Omron CX-Programmer project NewProject (CX-Programmer 9.11)

# PLC NewPLC1: CP1L M

## Global symbols (name address type ; comment)
AbsoluteActualPosition D0 DINT  ; Absolute Actual Position
ActualVelocity D2 DINT  ; Actual Velocity
A641.00 BOOL  ; $?St$Bk?_#[4] / Modbus-RTU Master Execution Bit / Turned ON: Execution Started / ON: Execution In Progress / OFF: Not Executed Or Execution completed.$?St$Bk?_#[4]
A641.01 BOOL  ; $?St$Bk?_#[5] / Modbus-RTU Master Execution Normal Flag / ON: Execution Normal / OFF: Execution Error Or Still In Progress$?St$Bk?_#[5]
A641.02 BOOL  ; $?St$Bk?_#[6] / Modbus-RTU Master Execution Error Flag / ON: Execution Error / OFF: Execution Normal Or Still In Progress$?St$Bk?_#[6]
D100 CHANNEL  ; Number Of Modbus Data Bytes
H0 CHANNEL  ; Input Status
H0.00 BOOL  ; Input 1
H0.01 BOOL  ; Input 2
H0.02 BOOL  ; Input 3
H0.03 BOOL  ; Input 4
H0.04 BOOL  ; Input 5
H0.05 BOOL  ; Input 6
H0.06 BOOL  ; Input 7
H0.07 BOOL  ; Input 8
H1 CHANNEL  ; Input Status
H10 CHANNEL  ; Output Status
H10.00 BOOL  ; Output 1
H10.01 BOOL  ; Output 2
H10.02 BOOL  ; Output 3
H10.03 BOOL  ; Output 4
H10.04 BOOL  ; Output 5
H10.05 BOOL  ; Output 6
H10.06 BOOL  ; Output 7
H10.07 BOOL  ; Output 8
H1.08 BOOL  ; Input 9
H1.09 BOOL  ; Input 10
H1.10 BOOL  ; Input 11
H1.11 BOOL  ; Input 12
H1.12 BOOL  ; Input 13
H1.13 BOOL  ; Input 14
H1.14 BOOL  ; Input 15
H1.15 BOOL  ; Input 16
H20 CHANNEL  ; Fault / Status Flags
H20.00 BOOL  ; $?St$Bk?_#[7] / Counter-Clockwise Limit Active (No Fault) "L02"$?St$Bk?_#[7]
H20.01 BOOL  ; $?St$Bk?_#[8] / Drive Enabled Condition "E"$?St$Bk?_#[8]
H21 CHANNEL  ; Fault / Status Flags
H21.00 BOOL  ; $?St$Bk?_#[9] / Encoder Feedback / Commutation Fault "F07"$?St$Bk?_#[9]
H21.01 BOOL  ; $?St$Bk?_#[10] / Fatal PLC Fault "F98"$?St$Bk?_#[10]
H21.02 BOOL  ; $?St$Bk?_#[11] / Fatal Sequence Program Fault "F97"$?St$Bk?_#[11]
H21.03 BOOL  ; $?St$Bk?_#[12] / Phasing Fault (Non-Fatal) "F51"$?St$Bk?_#[12]
H21.04 BOOL  ; $?St$Bk?_#[13] / Drive Over-Current Fault (Non-Fatal) "F52"$?St$Bk?_#[13]
H21.05 BOOL  ; $?St$Bk?_#[14] / Motor Over-Current Fault (Non-Fatal) "F53"$?St$Bk?_#[14]
H21.06 BOOL  ; $?St$Bk?_#[15] / Bus Under-Voltage Fault (Non-Fatal) "F54"$?St$Bk?_#[15]
H21.07 BOOL  ; $?St$Bk?_#[16] / Maximum Following-Error Fault (Non-Fatal) "F55"$?St$Bk?_#[16]
H21.08 BOOL  ; $?St$Bk?_#[17] / Velocity Regulation Fault (Non-Fatal) "F56"$?St$Bk?_#[17]
H21.09 BOOL  ; $?St$Bk?_#[18] / Serial Communications Fault (Non-Fatal) "F57"$?St$Bk?_#[18]
H21.10 BOOL  ; $?St$Bk?_#[19] / Positive Travel Limit Fault (Non-Fatal) "FL1"$?St$Bk?_#[19]
H21.11 BOOL  ; $?St$Bk?_#[20] / Negative Travel Limit Fault (Non-Fatal) "FL2"$?St$Bk?_#[20]
H21.12 BOOL  ; $?St$Bk?_#[21] / Sequential Program Execution Fault (Non-Fatal) "F58"$?St$Bk?_#[21]
H21.13 BOOL  ; $?St$Bk?_#[22] / Drive Disabled Condition "d"$?St$Bk?_#[22]
H21.14 BOOL  ; $?St$Bk?_#[23] / Phasing In Progress "P"$?St$Bk?_#[23]
H21.15 BOOL  ; $?St$Bk?_#[24] / Clockwise Travel Limit Active (No Fault) "L01"$?St$Bk?_#[24]
H22 CHANNEL  ; Fault / Status Flags
H22.00 BOOL  ; $?St$Bk?_#[25] / Processor Fault "F00"$?St$Bk?_#[25]
H22.01 BOOL  ; $?St$Bk?_#[26] / Drive Not Configured "F99"$?St$Bk?_#[26]
H22.03 BOOL  ; $?St$Bk?_#[28] / Bridge Hardware Fault "F02"$?St$Bk?_#[28]
H22.04 BOOL  ; $?St$Bk?_#[29] / Current Feedback Fault "F03"$?St$Bk?_#[29]
H22.05 BOOL  ; $?St$Bk?_#[30] / Current Regulation Fault "F04"$?St$Bk?_#[30]
H22.06 BOOL  ; $?St$Bk?_#[31] / Drive Over-Temperature Fault "F05"$?St$Bk?_#[31]
H22.07 BOOL  ; $?St$Bk?_#[32] / Motor Over-Temperature Fault "F06"$?St$Bk?_#[32]
W0.00 BOOL  ; Run Program 1
W0.01 BOOL  ; Run Program 2
W10.00 BOOL  ; Input 1
W10.01 BOOL  ; Input 2
W10.02 BOOL  ; Input 3
W10.03 BOOL  ; Input 4
W10.04 BOOL  ; Input 5
W10.05 BOOL  ; Input 6
W10.06 BOOL  ; Input 7
W10.07 BOOL  ; Input 8
W10.08 BOOL  ; Input 9
W10.09 BOOL  ; Input 10
W10.10 BOOL  ; Input 11
W10.11 BOOL  ; Input 12
W10.12 BOOL  ; Input 13
W10.13 BOOL  ; Input 14
W10.14 BOOL  ; Input 15
W10.15 BOOL  ; Input 16
W1.00 BOOL  ; Read Inputs
W1.01 BOOL  ; Read Outputs
W20.00 BOOL  ; Output 1
W20.01 BOOL  ; Output 2
W20.02 BOOL  ; Output 3
W20.03 BOOL  ; Output 4
W20.04 BOOL  ; Output 5
W20.05 BOOL  ; Output 6
W20.06 BOOL  ; Output 7
W20.07 BOOL  ; Output 8
W21.00 BOOL  ; $?St$Bk?_#[33] / Encoder Feedback / Commutation Fault "F07"$?St$Bk?_#[33]
W21.01 BOOL  ; $?St$Bk?_#[34] / Fatal PLC Fault "F98"$?St$Bk?_#[34]
W21.02 BOOL  ; $?St$Bk?_#[35] / Fatal Sequence Program Fault "F97"$?St$Bk?_#[35]
W21.03 BOOL  ; $?St$Bk?_#[36] / Phasing Fault (Non-Fatal) "F51"$?St$Bk?_#[36]
W21.04 BOOL  ; $?St$Bk?_#[37] / Drive Over-Current Fault (Non-Fatal) "F52"$?St$Bk?_#[37]
W21.05 BOOL  ; $?St$Bk?_#[38] / Motor Over-Current Fault (Non-Fatal) "F53"$?St$Bk?_#[38]
W21.06 BOOL  ; $?St$Bk?_#[39] / Bus Under-Voltage Fault (Non-Fatal) "F54"$?St$Bk?_#[39]
W21.07 BOOL  ; $?St$Bk?_#[40] / Maximum Following-Error Fault (Non-Fatal) "F55"$?St$Bk?_#[40]
W21.08 BOOL  ; $?St$Bk?_#[41] / Velocity Regulation Fault (Non-Fatal) "F56"$?St$Bk?_#[41]
W21.09 BOOL  ; $?St$Bk?_#[42] / Serial Communications Fault (Non-Fatal) "F57"$?St$Bk?_#[42]
W21.10 BOOL  ; $?St$Bk?_#[43] / Positive Travel Limit Fault (Non-Fatal) "FL1"$?St$Bk?_#[43]
W21.11 BOOL  ; $?St$Bk?_#[44] / Negative Travel Limit Fault (Non-Fatal) "FL2"$?St$Bk?_#[44]
W21.12 BOOL  ; $?St$Bk?_#[45] / Sequential Program Execution Fault (Non-Fatal) "F58"$?St$Bk?_#[45]
W21.13 BOOL  ; $?St$Bk?_#[46] / Drive Disabled Condition "d"$?St$Bk?_#[46]
W21.14 BOOL  ; $?St$Bk?_#[47] / Phasing In Progress "P"$?St$Bk?_#[47]
W21.15 BOOL  ; $?St$Bk?_#[48] / Clockwise Travel Limit Active (No Fault) "L01"$?St$Bk?_#[48]
W22.00 BOOL  ; $?St$Bk?_#[49] / Processor Fault "F00"$?St$Bk?_#[49]
W22.01 BOOL  ; $?St$Bk?_#[50] / Drive Not Configured "F99"$?St$Bk?_#[50]
W22.03 BOOL  ; $?St$Bk?_#[52] / Bridge Hardware Fault "F02"$?St$Bk?_#[52]
W22.04 BOOL  ; $?St$Bk?_#[53] / Current Feedback Fault "F03"$?St$Bk?_#[53]
W22.05 BOOL  ; $?St$Bk?_#[54] / Current Regulation Fault "F04"$?St$Bk?_#[54]
W22.06 BOOL  ; $?St$Bk?_#[55] / Drive Over-Temperature Fault "F05"$?St$Bk?_#[55]
W22.07 BOOL  ; $?St$Bk?_#[56] / Motor Over-Temperature Fault "F06"$?St$Bk?_#[56]
W2.00 BOOL  ; Read Absolute Actual Position
W2.01 BOOL  ; Read Actual Velocity
W2.02 BOOL  ; Read Torque Output
W30.00 BOOL  ; $?St$Bk?_#[57] / Counter-Clockwise Limit Active (No Fault) "L02"$?St$Bk?_#[57]
W30.01 BOOL  ; $?St$Bk?_#[58] / Drive Enabled Condition "E"$?St$Bk?_#[58]
W3.00 BOOL  ; Preset Actual Position
W3.01 BOOL  ; Preset Actual Velocity
W4.00 BOOL  ; Report Slave ID
CommandCommunicationsDataWord1 D32203 CHANNEL  ; Command Communications Data - Word 1 (94 Bytes Maximum)
CommandCommunicationsDataWord2 D32204 CHANNEL  ; Command Communications Data - Word 2 (94 Bytes Maximum)
CommandCommunicationsDataWord3 D32205 CHANNEL  ; Command Communications Data - Word 3 (94 Bytes Maximum)
CommandCommunicationsDataWord4 D32206 CHANNEL  ; Command Communications Data - Word 4 (94 Bytes Maximum)
CommandCommunicationsDataWord5 D32207 CHANNEL  ; Command Communications Data - Word 5 (94 Bytes Maximum)
CommandFunctionCode D32201 CHANNEL  ; $?St$Bk?_#[59] / Command Function Code / Bits 0-7 (*8-15 = 00)$?St$Bk?_#[59]
CommandNumberOfCommunicationBytes D32202 CHANNEL  ; Command Number Of Communications Data Bytes (0000 To 005E HEX)
CommandSlaveAddress D32200 CHANNEL  ; $?St$Bk?_#[60] / Command Slave Address (00 To F7 HEX) / Bits 0-7 (*8-15 = 00)$?St$Bk?_#[60]
PositionRAM_RegisterValue D10 DINT  ; Position RAM Register Value
ResponseCommunicationDataWord1 D32254 CHANNEL  ; Response Communications Data - Word 1 (92 Bytes Maximum)
ResponseCommunicationsDataWord1 D32254 CHANNEL  ; Response Communications Data - Word 1 (92 Bytes Maximum)
ResponseCommunicationsDataWord2 D32255 CHANNEL  ; Response Communications Data - Word 2 (92 Bytes Maximum)
ResponseCommunicationsDataWord3 D32256 CHANNEL  ; Response Communications Data - Word 3 (92 Bytes Maximum)
ResponseCommunicationsDataWord4 D32257 CHANNEL  ; Response Communications Data - Word 4 (92 Bytes Maximum)
ResponseCommunicationsDataWord5 D32258 CHANNEL  ; Response Communications Data - Word 5 (92 Bytes Maximum)
ResponseErrorCode D32252 CHANNEL  ; $?St$Bk?_#[61] / Response Error Code / Bits 0-7 (*8-15 = 00)$?St$Bk?_#[61]
ResponseFunctionCode D32251 CHANNEL  ; $?St$Bk?_#[62] / Response Function Code / Bits 0-7 (*8-15 = 00)$?St$Bk?_#[62]
ResponseNumberOfCommunicationBytes D32253 CHANNEL  ; Response Number Of Response Data Bytes (0000 To 03EA HEX)
ResponseSlaveAddress D32250 CHANNEL  ; $?St$Bk?_#[63] / Response Slave Address (00 To F7 HEX) / Bits 0-7 (*8-15 = 00)$?St$Bk?_#[63]
TorqueOutput D4 DINT  ; Torque Output
VelocityRAM_RegisterValue D12 DINT  ; Velocity RAM Register Value

## Program NewProgram1 (cyclic task 0)
; ***SIMPLE MODBUS Communications:  CP1L-M Serial Port 1 To Axiom Plus PV10 / Reference CP1L Operation Manual Section 6-3-3 (W462) & Axiom Plus PV Series User Manual Chapter 13 (3600-4628) & Modicon Modbus Protocol Reference Guide (PI–MBUS–300) / 01 Read Coil Status / 02 Read Input Status / 03 Read Holding Registers / 05 Force Single Coil / 15 Force Multiple Coils / 16 Preset Multiple Registers / 17 Report Slave ID

### Section Section1

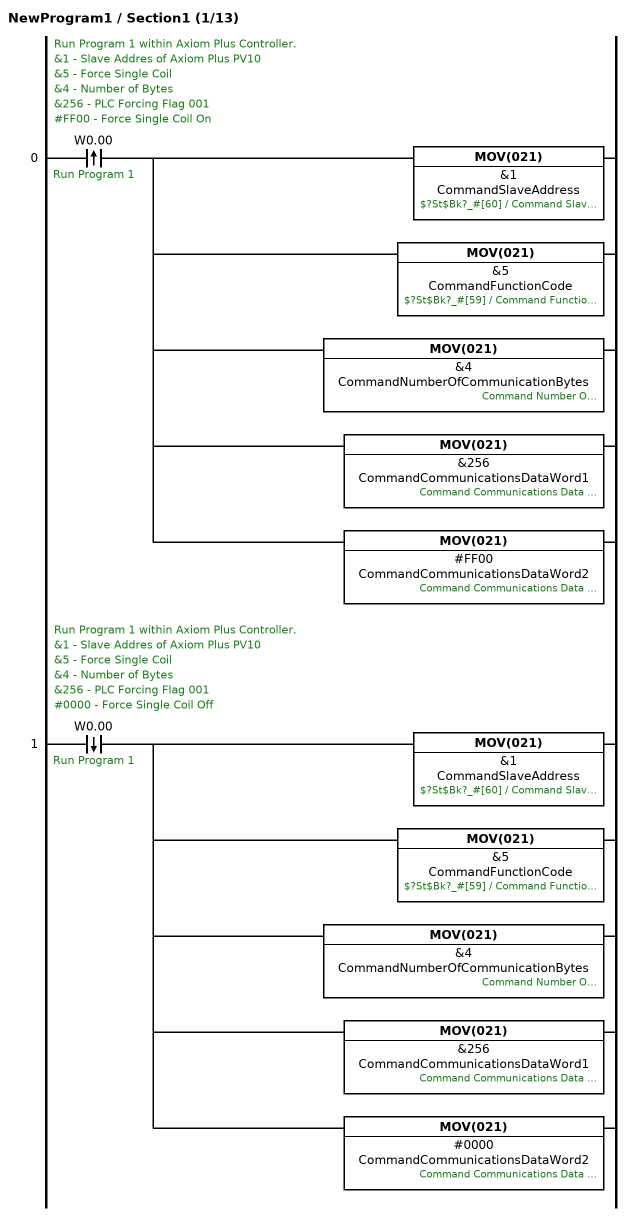
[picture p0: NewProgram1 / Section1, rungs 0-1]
; rung 0: Run Program 1 within Axiom Plus Controller. / &1 - Slave Addres of Axiom Plus PV10 / &5 - Force Single Coil / &4 - Number of Bytes / &256 - PLC Forcing Flag 001 / #FF00 - Force Single Coil On
@LD W0.00  ; Run Program 1
MOV(021) &1 CommandSlaveAddress  ; $?St$Bk?_#[60] / Command Slave Address (00 To F7 HEX) / Bits 0-7 (*8-15 = 00)$?St$Bk?_#[60]
MOV(021) &5 CommandFunctionCode  ; $?St$Bk?_#[59] / Command Function Code / Bits 0-7 (*8-15 = 00)$?St$Bk?_#[59]
MOV(021) &4 CommandNumberOfCommunicationBytes  ; Command Number Of Communications Data Bytes (0000 To 005E HEX)
MOV(021) &256 CommandCommunicationsDataWord1  ; Command Communications Data - Word 1 (94 Bytes Maximum)
MOV(021) #FF00 CommandCommunicationsDataWord2  ; Command Communications Data - Word 2 (94 Bytes Maximum)
; rung 1: Run Program 1 within Axiom Plus Controller. / &1 - Slave Addres of Axiom Plus PV10 / &5 - Force Single Coil / &4 - Number of Bytes / &256 - PLC Forcing Flag 001 / #0000 - Force Single Coil Off
%LD W0.00  ; Run Program 1
MOV(021) &1 CommandSlaveAddress  ; $?St$Bk?_#[60] / Command Slave Address (00 To F7 HEX) / Bits 0-7 (*8-15 = 00)$?St$Bk?_#[60]
MOV(021) &5 CommandFunctionCode  ; $?St$Bk?_#[59] / Command Function Code / Bits 0-7 (*8-15 = 00)$?St$Bk?_#[59]
MOV(021) &4 CommandNumberOfCommunicationBytes  ; Command Number Of Communications Data Bytes (0000 To 005E HEX)
MOV(021) &256 CommandCommunicationsDataWord1  ; Command Communications Data - Word 1 (94 Bytes Maximum)
MOV(021) #0000 CommandCommunicationsDataWord2  ; Command Communications Data - Word 2 (94 Bytes Maximum)

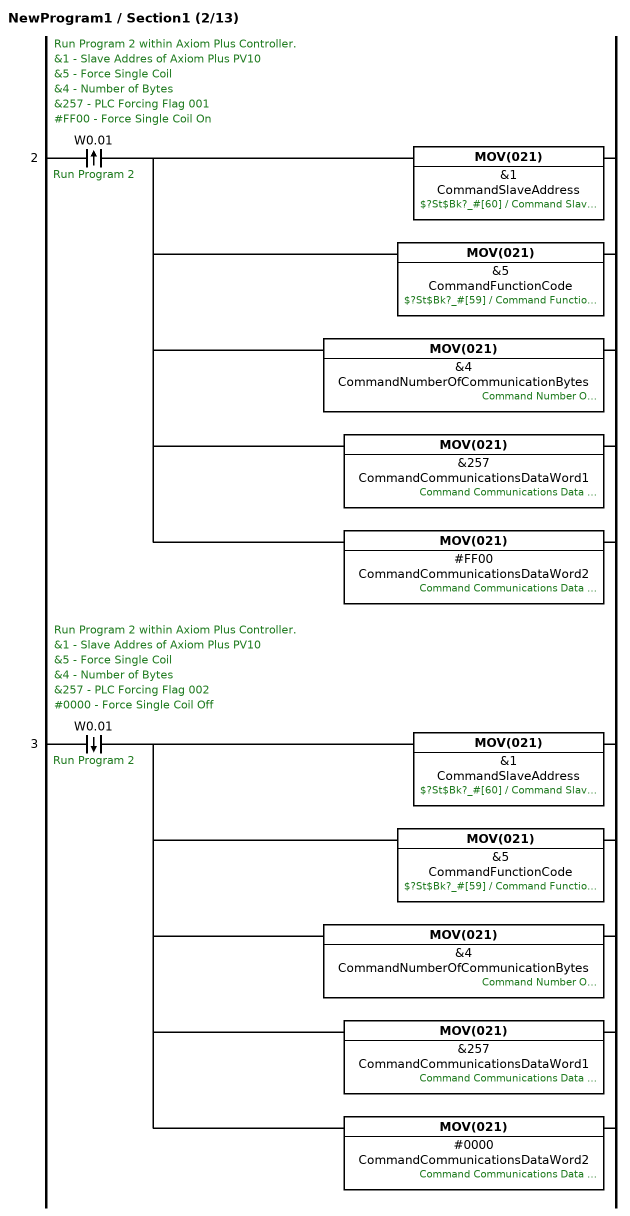
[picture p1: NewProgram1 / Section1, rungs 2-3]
; rung 2: Run Program 2 within Axiom Plus Controller. / &1 - Slave Addres of Axiom Plus PV10 / &5 - Force Single Coil / &4 - Number of Bytes / &257 - PLC Forcing Flag 001 / #FF00 - Force Single Coil On
@LD W0.01  ; Run Program 2
MOV(021) &1 CommandSlaveAddress  ; $?St$Bk?_#[60] / Command Slave Address (00 To F7 HEX) / Bits 0-7 (*8-15 = 00)$?St$Bk?_#[60]
MOV(021) &5 CommandFunctionCode  ; $?St$Bk?_#[59] / Command Function Code / Bits 0-7 (*8-15 = 00)$?St$Bk?_#[59]
MOV(021) &4 CommandNumberOfCommunicationBytes  ; Command Number Of Communications Data Bytes (0000 To 005E HEX)
MOV(021) &257 CommandCommunicationsDataWord1  ; Command Communications Data - Word 1 (94 Bytes Maximum)
MOV(021) #FF00 CommandCommunicationsDataWord2  ; Command Communications Data - Word 2 (94 Bytes Maximum)
; rung 3: Run Program 2 within Axiom Plus Controller. / &1 - Slave Addres of Axiom Plus PV10 / &5 - Force Single Coil / &4 - Number of Bytes / &257 - PLC Forcing Flag 002 / #0000 - Force Single Coil Off
%LD W0.01  ; Run Program 2
MOV(021) &1 CommandSlaveAddress  ; $?St$Bk?_#[60] / Command Slave Address (00 To F7 HEX) / Bits 0-7 (*8-15 = 00)$?St$Bk?_#[60]
MOV(021) &5 CommandFunctionCode  ; $?St$Bk?_#[59] / Command Function Code / Bits 0-7 (*8-15 = 00)$?St$Bk?_#[59]
MOV(021) &4 CommandNumberOfCommunicationBytes  ; Command Number Of Communications Data Bytes (0000 To 005E HEX)
MOV(021) &257 CommandCommunicationsDataWord1  ; Command Communications Data - Word 1 (94 Bytes Maximum)
MOV(021) #0000 CommandCommunicationsDataWord2  ; Command Communications Data - Word 2 (94 Bytes Maximum)

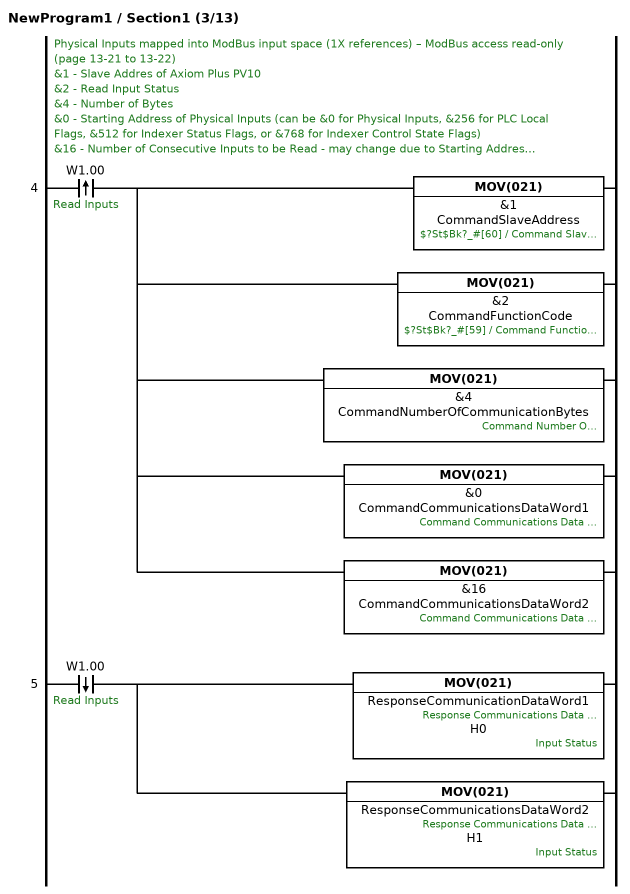
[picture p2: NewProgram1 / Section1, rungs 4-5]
; rung 4: Physical Inputs mapped into ModBus input space (1X references) – ModBus access read-only (page 13-21 to 13-22) / &1 - Slave Addres of Axiom Plus PV10 / &2 - Read Input Status / &4 - Number of Bytes / &0 - Starting Address of Physical Inputs (can be &0 for Physical Inputs, &256 for PLC Local Flags, &512 for Indexer Status Flags, or &768 for Indexer Control State Flags) / &16 - Number of Consecutive Inputs to be Read - may change due to Starting Address (Input 1 is at D32254.0, Input 8 is at D32254.7, Input 9 is at D32255.8, and Input 16 is at D32255.15)
@LD W1.00  ; Read Inputs
MOV(021) &1 CommandSlaveAddress  ; $?St$Bk?_#[60] / Command Slave Address (00 To F7 HEX) / Bits 0-7 (*8-15 = 00)$?St$Bk?_#[60]
MOV(021) &2 CommandFunctionCode  ; $?St$Bk?_#[59] / Command Function Code / Bits 0-7 (*8-15 = 00)$?St$Bk?_#[59]
MOV(021) &4 CommandNumberOfCommunicationBytes  ; Command Number Of Communications Data Bytes (0000 To 005E HEX)
MOV(021) &0 CommandCommunicationsDataWord1  ; Command Communications Data - Word 1 (94 Bytes Maximum)
MOV(021) &16 CommandCommunicationsDataWord2  ; Command Communications Data - Word 2 (94 Bytes Maximum)
; rung 5
%LD W1.00  ; Read Inputs
MOV(021) ResponseCommunicationDataWord1 H0  ; Response Communications Data - Word 1 (92 Bytes Maximum), Input Status
MOV(021) ResponseCommunicationsDataWord2 H1  ; Response Communications Data - Word 2 (92 Bytes Maximum), Input Status

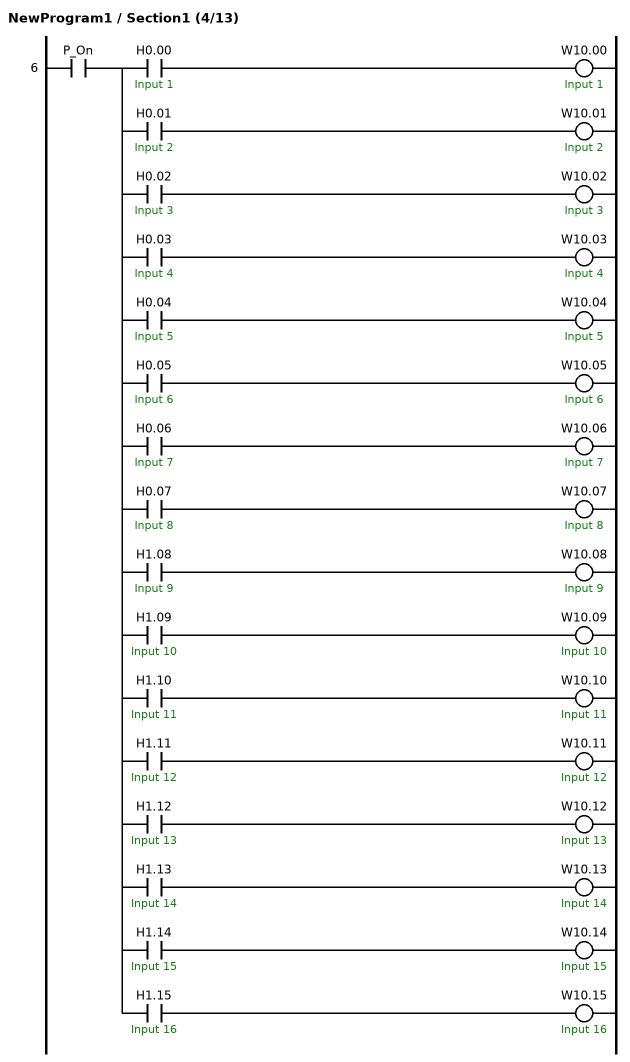
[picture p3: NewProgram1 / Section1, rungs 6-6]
; rung 6
LD P_On
OUT TR0
AND H0.00  ; Input 1
OUT W10.00  ; Input 1
LD TR0
AND H0.01  ; Input 2
OUT W10.01  ; Input 2
LD TR0
AND H0.02  ; Input 3
OUT W10.02  ; Input 3
LD TR0
AND H0.03  ; Input 4
OUT W10.03  ; Input 4
LD TR0
AND H0.04  ; Input 5
OUT W10.04  ; Input 5
LD TR0
AND H0.05  ; Input 6
OUT W10.05  ; Input 6
LD TR0
AND H0.06  ; Input 7
OUT W10.06  ; Input 7
LD TR0
AND H0.07  ; Input 8
OUT W10.07  ; Input 8
LD TR0
AND H1.08  ; Input 9
OUT W10.08  ; Input 9
LD TR0
AND H1.09  ; Input 10
OUT W10.09  ; Input 10
LD TR0
AND H1.10  ; Input 11
OUT W10.10  ; Input 11
LD TR0
AND H1.11  ; Input 12
OUT W10.11  ; Input 12
LD TR0
AND H1.12  ; Input 13
OUT W10.12  ; Input 13
LD TR0
AND H1.13  ; Input 14
OUT W10.13  ; Input 14
LD TR0
AND H1.14  ; Input 15
OUT W10.14  ; Input 15
LD TR0
AND H1.15  ; Input 16
OUT W10.15  ; Input 16

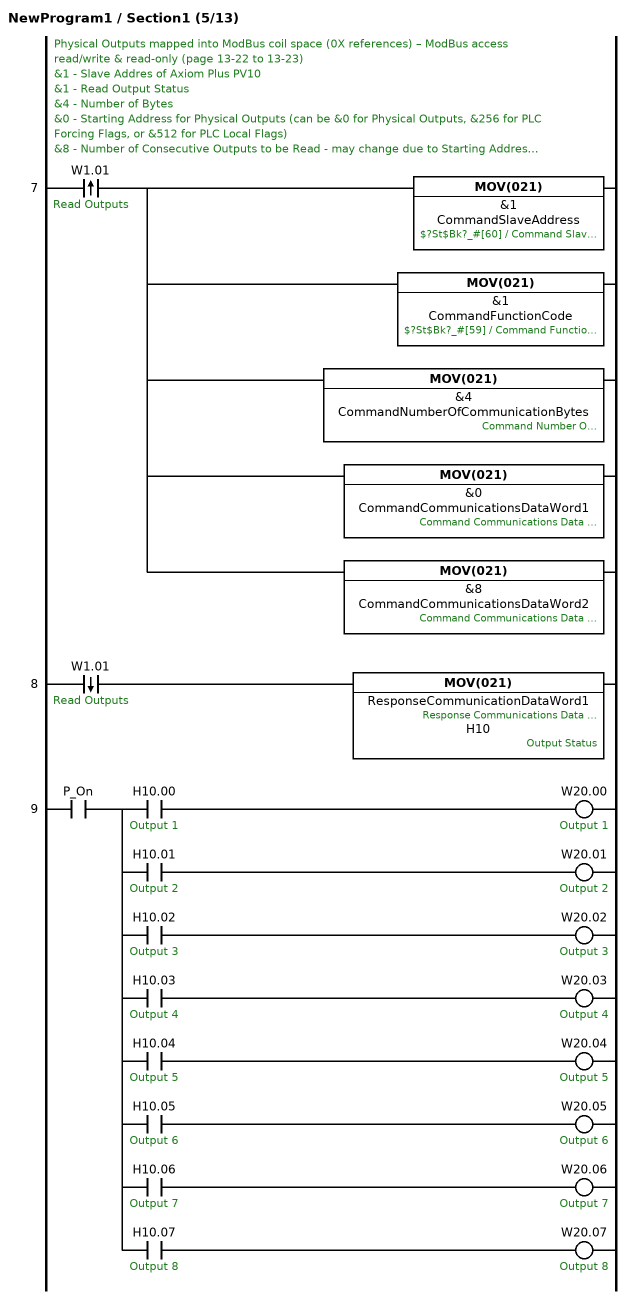
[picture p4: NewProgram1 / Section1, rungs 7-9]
; rung 7: Physical Outputs mapped into ModBus coil space (0X references) – ModBus access read/write & read-only (page 13-22 to 13-23) / &1 - Slave Addres of Axiom Plus PV10 / &1 - Read Output Status / &4 - Number of Bytes / &0 - Starting Address for Physical Outputs (can be &0 for Physical Outputs, &256 for PLC Forcing Flags, or &512 for PLC Local Flags) / &8 - Number of Consecutive Outputs to be Read - may change due to Starting Address (Output 1 is at D32254.0, Output 8 is at D32254.7, Output 9 is at D32255.8, and Output 16 is at D32255.15)
@LD W1.01  ; Read Outputs
MOV(021) &1 CommandSlaveAddress  ; $?St$Bk?_#[60] / Command Slave Address (00 To F7 HEX) / Bits 0-7 (*8-15 = 00)$?St$Bk?_#[60]
MOV(021) &1 CommandFunctionCode  ; $?St$Bk?_#[59] / Command Function Code / Bits 0-7 (*8-15 = 00)$?St$Bk?_#[59]
MOV(021) &4 CommandNumberOfCommunicationBytes  ; Command Number Of Communications Data Bytes (0000 To 005E HEX)
MOV(021) &0 CommandCommunicationsDataWord1  ; Command Communications Data - Word 1 (94 Bytes Maximum)
MOV(021) &8 CommandCommunicationsDataWord2  ; Command Communications Data - Word 2 (94 Bytes Maximum)
; rung 8
%LD W1.01  ; Read Outputs
MOV(021) ResponseCommunicationDataWord1 H10  ; Response Communications Data - Word 1 (92 Bytes Maximum), Output Status
; rung 9
LD P_On
OUT TR0
AND H10.00  ; Output 1
OUT W20.00  ; Output 1
LD TR0
AND H10.01  ; Output 2
OUT W20.01  ; Output 2
LD TR0
AND H10.02  ; Output 3
OUT W20.02  ; Output 3
LD TR0
AND H10.03  ; Output 4
OUT W20.03  ; Output 4
LD TR0
AND H10.04  ; Output 5
OUT W20.04  ; Output 5
LD TR0
AND H10.05  ; Output 6
OUT W20.05  ; Output 6
LD TR0
AND H10.06  ; Output 7
OUT W20.06  ; Output 7
LD TR0
AND H10.07  ; Output 8
OUT W20.07  ; Output 8

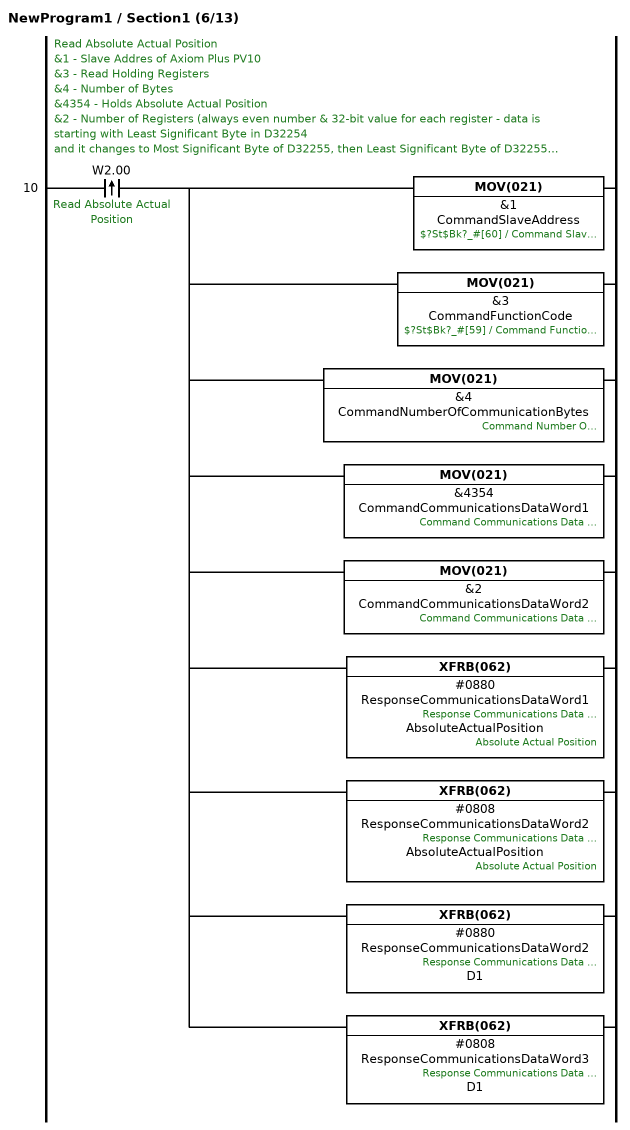
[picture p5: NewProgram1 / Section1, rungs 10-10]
; rung 10: Read Absolute Actual Position / &1 - Slave Addres of Axiom Plus PV10 / &3 - Read Holding Registers / &4 - Number of Bytes / &4354 - Holds Absolute Actual Position / &2 - Number of Registers (always even number & 32-bit value for each register - data is starting with Least Significant Byte in D32254 / and it changes to Most Significant Byte of D32255, then Least Significant Byte of D32255, then Most Significant Byte of D32256) / For instance, a value returned of &4000 means 4.000 inches.
@LD W2.00  ; Read Absolute Actual Position
MOV(021) &1 CommandSlaveAddress  ; $?St$Bk?_#[60] / Command Slave Address (00 To F7 HEX) / Bits 0-7 (*8-15 = 00)$?St$Bk?_#[60]
MOV(021) &3 CommandFunctionCode  ; $?St$Bk?_#[59] / Command Function Code / Bits 0-7 (*8-15 = 00)$?St$Bk?_#[59]
MOV(021) &4 CommandNumberOfCommunicationBytes  ; Command Number Of Communications Data Bytes (0000 To 005E HEX)
MOV(021) &4354 CommandCommunicationsDataWord1  ; Command Communications Data - Word 1 (94 Bytes Maximum)
MOV(021) &2 CommandCommunicationsDataWord2  ; Command Communications Data - Word 2 (94 Bytes Maximum)
XFRB(062) #0880 ResponseCommunicationsDataWord1 AbsoluteActualPosition  ; Response Communications Data - Word 1 (92 Bytes Maximum), Absolute Actual Position
XFRB(062) #0808 ResponseCommunicationsDataWord2 AbsoluteActualPosition  ; Response Communications Data - Word 2 (92 Bytes Maximum), Absolute Actual Position
XFRB(062) #0880 ResponseCommunicationsDataWord2 D1  ; Response Communications Data - Word 2 (92 Bytes Maximum)
XFRB(062) #0808 ResponseCommunicationsDataWord3 D1  ; Response Communications Data - Word 3 (92 Bytes Maximum)

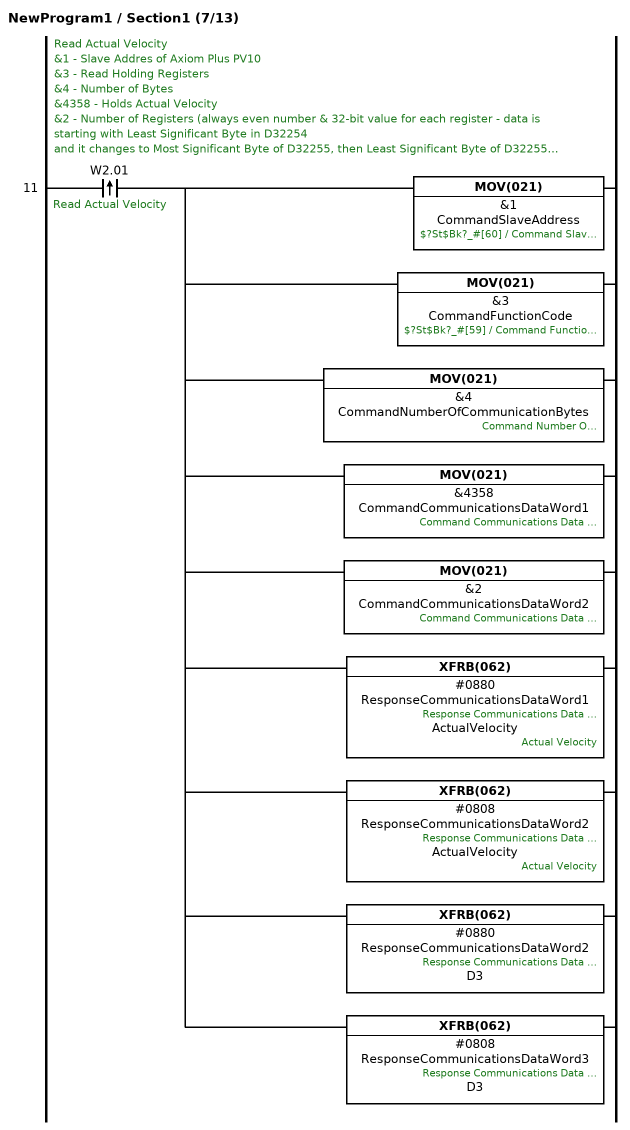
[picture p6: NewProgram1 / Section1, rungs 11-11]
; rung 11: Read Actual Velocity / &1 - Slave Addres of Axiom Plus PV10 / &3 - Read Holding Registers / &4 - Number of Bytes / &4358 - Holds Actual Velocity / &2 - Number of Registers (always even number & 32-bit value for each register - data is starting with Least Significant Byte in D32254 / and it changes to Most Significant Byte of D32255, then Least Significant Byte of D32255, then Most Significant Byte of D32256) / For instance, a value returned of &1000 means 10.00 inches/second.
@LD W2.01  ; Read Actual Velocity
MOV(021) &1 CommandSlaveAddress  ; $?St$Bk?_#[60] / Command Slave Address (00 To F7 HEX) / Bits 0-7 (*8-15 = 00)$?St$Bk?_#[60]
MOV(021) &3 CommandFunctionCode  ; $?St$Bk?_#[59] / Command Function Code / Bits 0-7 (*8-15 = 00)$?St$Bk?_#[59]
MOV(021) &4 CommandNumberOfCommunicationBytes  ; Command Number Of Communications Data Bytes (0000 To 005E HEX)
MOV(021) &4358 CommandCommunicationsDataWord1  ; Command Communications Data - Word 1 (94 Bytes Maximum)
MOV(021) &2 CommandCommunicationsDataWord2  ; Command Communications Data - Word 2 (94 Bytes Maximum)
XFRB(062) #0880 ResponseCommunicationsDataWord1 ActualVelocity  ; Response Communications Data - Word 1 (92 Bytes Maximum), Actual Velocity
XFRB(062) #0808 ResponseCommunicationsDataWord2 ActualVelocity  ; Response Communications Data - Word 2 (92 Bytes Maximum), Actual Velocity
XFRB(062) #0880 ResponseCommunicationsDataWord2 D3  ; Response Communications Data - Word 2 (92 Bytes Maximum)
XFRB(062) #0808 ResponseCommunicationsDataWord3 D3  ; Response Communications Data - Word 3 (92 Bytes Maximum)

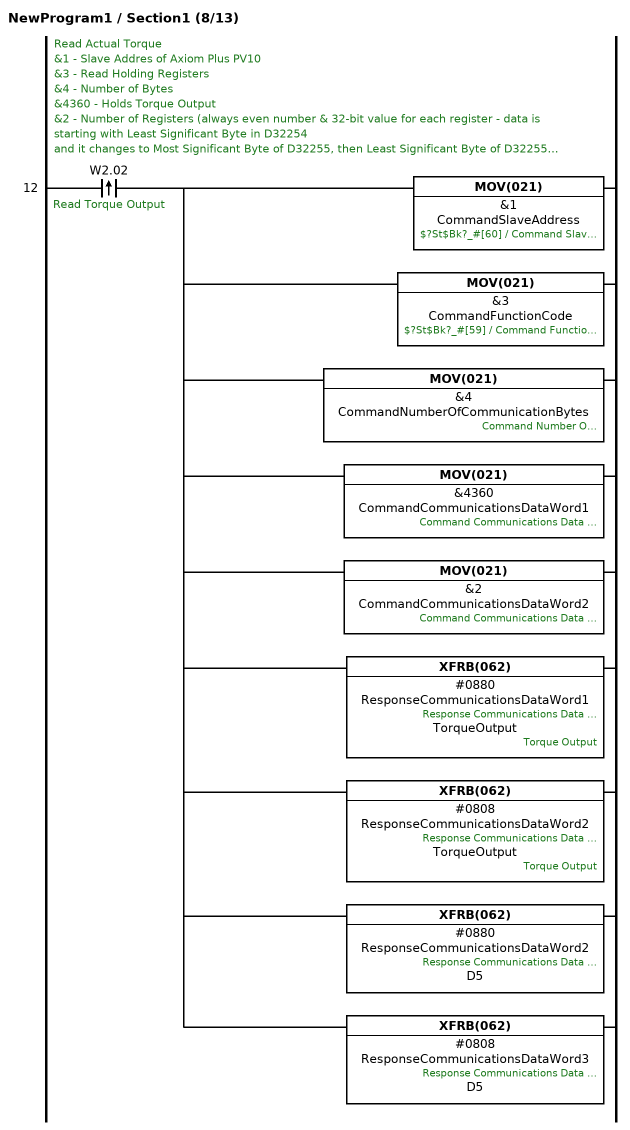
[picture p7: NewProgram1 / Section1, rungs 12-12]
; rung 12: Read Actual Torque / &1 - Slave Addres of Axiom Plus PV10 / &3 - Read Holding Registers / &4 - Number of Bytes / &4360 - Holds Torque Output / &2 - Number of Registers (always even number & 32-bit value for each register - data is starting with Least Significant Byte in D32254 / and it changes to Most Significant Byte of D32255, then Least Significant Byte of D32255, then Most Significant Byte of D32256)
@LD W2.02  ; Read Torque Output
MOV(021) &1 CommandSlaveAddress  ; $?St$Bk?_#[60] / Command Slave Address (00 To F7 HEX) / Bits 0-7 (*8-15 = 00)$?St$Bk?_#[60]
MOV(021) &3 CommandFunctionCode  ; $?St$Bk?_#[59] / Command Function Code / Bits 0-7 (*8-15 = 00)$?St$Bk?_#[59]
MOV(021) &4 CommandNumberOfCommunicationBytes  ; Command Number Of Communications Data Bytes (0000 To 005E HEX)
MOV(021) &4360 CommandCommunicationsDataWord1  ; Command Communications Data - Word 1 (94 Bytes Maximum)
MOV(021) &2 CommandCommunicationsDataWord2  ; Command Communications Data - Word 2 (94 Bytes Maximum)
XFRB(062) #0880 ResponseCommunicationsDataWord1 TorqueOutput  ; Response Communications Data - Word 1 (92 Bytes Maximum), Torque Output
XFRB(062) #0808 ResponseCommunicationsDataWord2 TorqueOutput  ; Response Communications Data - Word 2 (92 Bytes Maximum), Torque Output
XFRB(062) #0880 ResponseCommunicationsDataWord2 D5  ; Response Communications Data - Word 2 (92 Bytes Maximum)
XFRB(062) #0808 ResponseCommunicationsDataWord3 D5  ; Response Communications Data - Word 3 (92 Bytes Maximum)

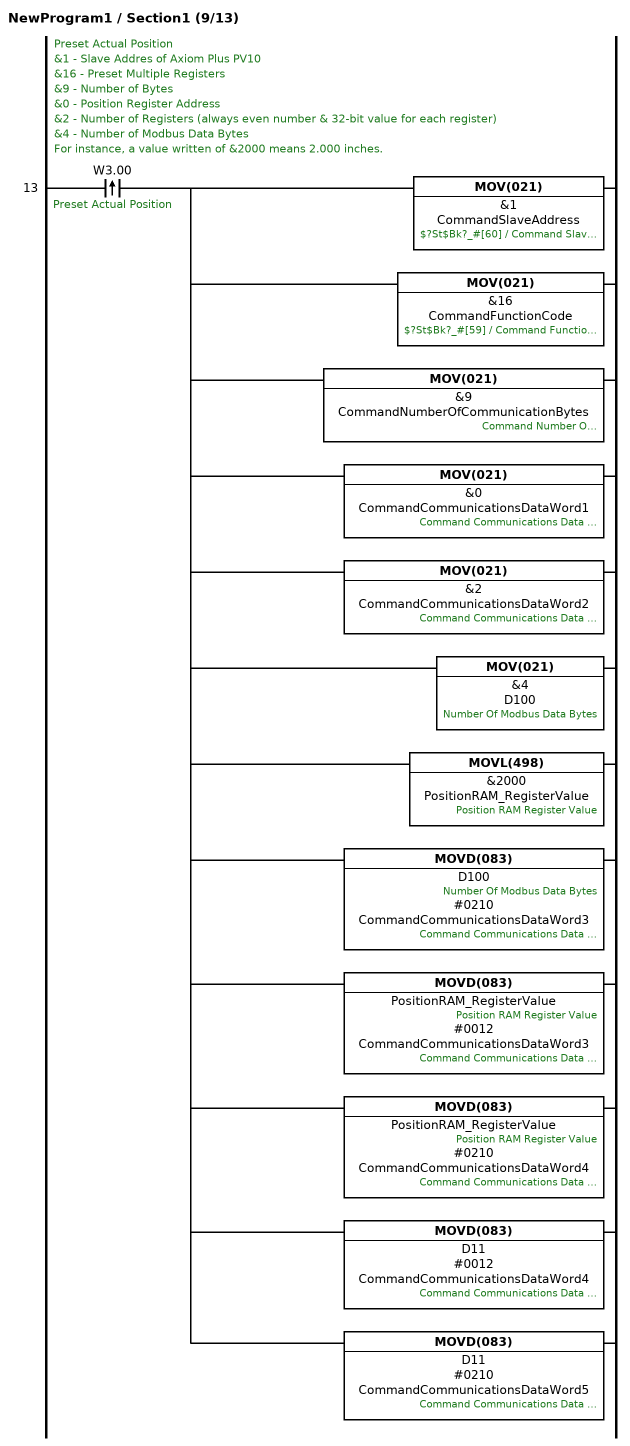
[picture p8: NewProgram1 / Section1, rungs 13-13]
; rung 13: Preset Actual Position / &1 - Slave Addres of Axiom Plus PV10 / &16 - Preset Multiple Registers / &9 - Number of Bytes / &0 - Position Register Address / &2 - Number of Registers (always even number & 32-bit value for each register) / &4 - Number of Modbus Data Bytes / For instance, a value written of &2000 means 2.000 inches.
@LD W3.00  ; Preset Actual Position
MOV(021) &1 CommandSlaveAddress  ; $?St$Bk?_#[60] / Command Slave Address (00 To F7 HEX) / Bits 0-7 (*8-15 = 00)$?St$Bk?_#[60]
MOV(021) &16 CommandFunctionCode  ; $?St$Bk?_#[59] / Command Function Code / Bits 0-7 (*8-15 = 00)$?St$Bk?_#[59]
MOV(021) &9 CommandNumberOfCommunicationBytes  ; Command Number Of Communications Data Bytes (0000 To 005E HEX)
MOV(021) &0 CommandCommunicationsDataWord1  ; Command Communications Data - Word 1 (94 Bytes Maximum)
MOV(021) &2 CommandCommunicationsDataWord2  ; Command Communications Data - Word 2 (94 Bytes Maximum)
MOV(021) &4 D100  ; Number Of Modbus Data Bytes
MOVL(498) &2000 PositionRAM_RegisterValue  ; Position RAM Register Value
MOVD(083) D100 #0210 CommandCommunicationsDataWord3  ; Number Of Modbus Data Bytes, Command Communications Data - Word 3 (94 Bytes Maximum)
MOVD(083) PositionRAM_RegisterValue #0012 CommandCommunicationsDataWord3  ; Position RAM Register Value, Command Communications Data - Word 3 (94 Bytes Maximum)
MOVD(083) PositionRAM_RegisterValue #0210 CommandCommunicationsDataWord4  ; Position RAM Register Value, Command Communications Data - Word 4 (94 Bytes Maximum)
MOVD(083) D11 #0012 CommandCommunicationsDataWord4  ; Command Communications Data - Word 4 (94 Bytes Maximum)
MOVD(083) D11 #0210 CommandCommunicationsDataWord5  ; Command Communications Data - Word 5 (94 Bytes Maximum)

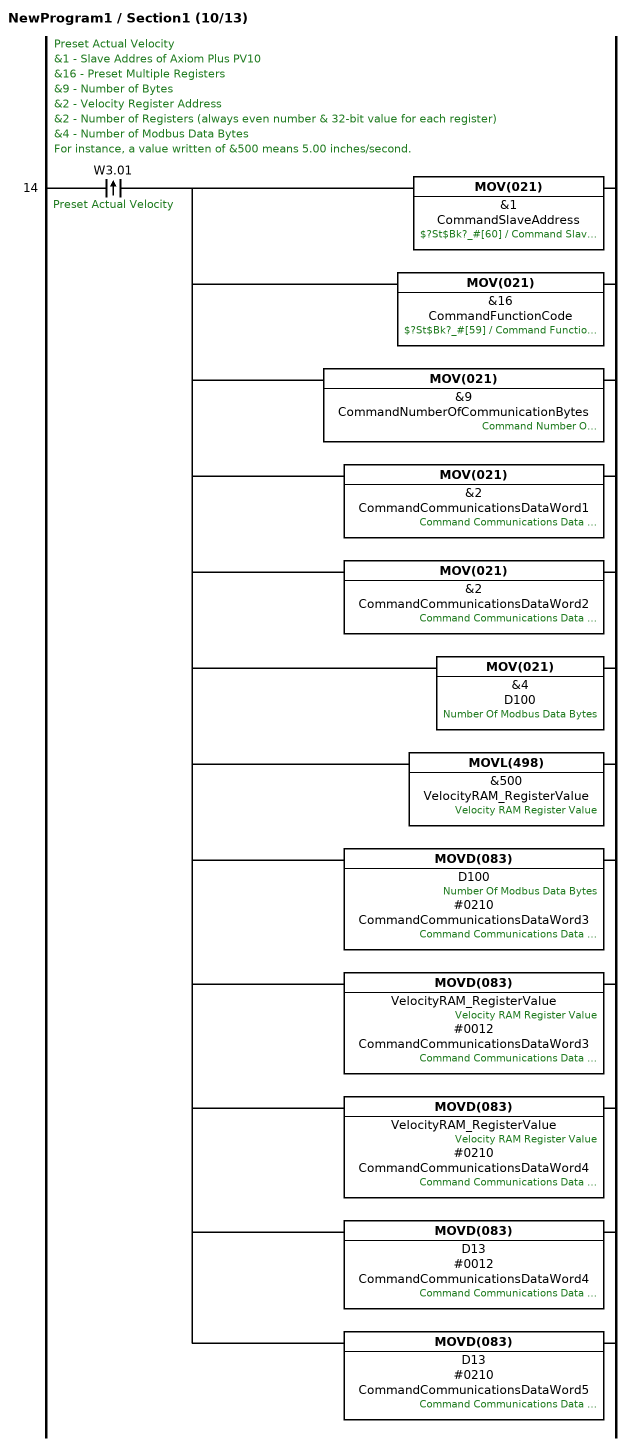
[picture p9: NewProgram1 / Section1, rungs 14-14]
; rung 14: Preset Actual Velocity / &1 - Slave Addres of Axiom Plus PV10 / &16 - Preset Multiple Registers / &9 - Number of Bytes / &2 - Velocity Register Address / &2 - Number of Registers (always even number & 32-bit value for each register) / &4 - Number of Modbus Data Bytes / For instance, a value written of &500 means 5.00 inches/second.
@LD W3.01  ; Preset Actual Velocity
MOV(021) &1 CommandSlaveAddress  ; $?St$Bk?_#[60] / Command Slave Address (00 To F7 HEX) / Bits 0-7 (*8-15 = 00)$?St$Bk?_#[60]
MOV(021) &16 CommandFunctionCode  ; $?St$Bk?_#[59] / Command Function Code / Bits 0-7 (*8-15 = 00)$?St$Bk?_#[59]
MOV(021) &9 CommandNumberOfCommunicationBytes  ; Command Number Of Communications Data Bytes (0000 To 005E HEX)
MOV(021) &2 CommandCommunicationsDataWord1  ; Command Communications Data - Word 1 (94 Bytes Maximum)
MOV(021) &2 CommandCommunicationsDataWord2  ; Command Communications Data - Word 2 (94 Bytes Maximum)
MOV(021) &4 D100  ; Number Of Modbus Data Bytes
MOVL(498) &500 VelocityRAM_RegisterValue  ; Velocity RAM Register Value
MOVD(083) D100 #0210 CommandCommunicationsDataWord3  ; Number Of Modbus Data Bytes, Command Communications Data - Word 3 (94 Bytes Maximum)
MOVD(083) VelocityRAM_RegisterValue #0012 CommandCommunicationsDataWord3  ; Velocity RAM Register Value, Command Communications Data - Word 3 (94 Bytes Maximum)
MOVD(083) VelocityRAM_RegisterValue #0210 CommandCommunicationsDataWord4  ; Velocity RAM Register Value, Command Communications Data - Word 4 (94 Bytes Maximum)
MOVD(083) D13 #0012 CommandCommunicationsDataWord4  ; Command Communications Data - Word 4 (94 Bytes Maximum)
MOVD(083) D13 #0210 CommandCommunicationsDataWord5  ; Command Communications Data - Word 5 (94 Bytes Maximum)

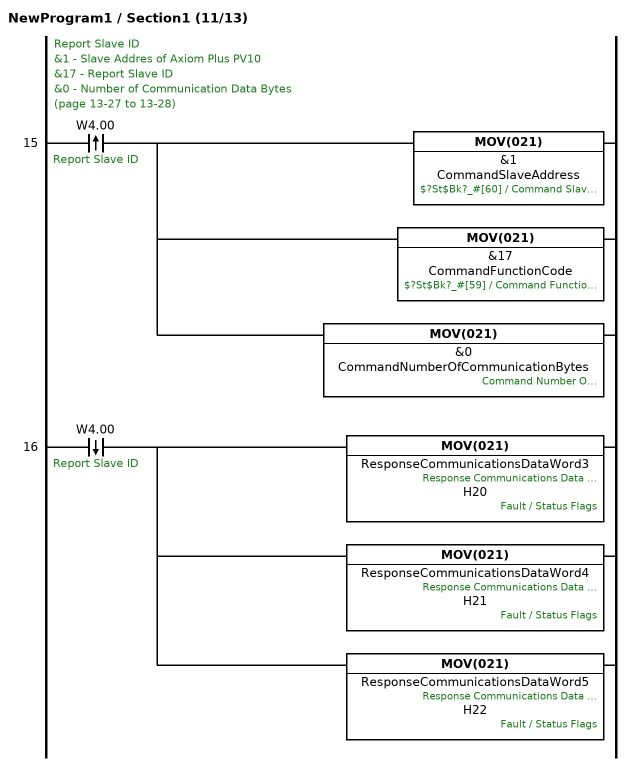
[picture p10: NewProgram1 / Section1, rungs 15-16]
; rung 15: Report Slave ID / &1 - Slave Addres of Axiom Plus PV10 / &17 - Report Slave ID / &0 - Number of Communication Data Bytes / (page 13-27 to 13-28)
@LD W4.00  ; Report Slave ID
MOV(021) &1 CommandSlaveAddress  ; $?St$Bk?_#[60] / Command Slave Address (00 To F7 HEX) / Bits 0-7 (*8-15 = 00)$?St$Bk?_#[60]
MOV(021) &17 CommandFunctionCode  ; $?St$Bk?_#[59] / Command Function Code / Bits 0-7 (*8-15 = 00)$?St$Bk?_#[59]
MOV(021) &0 CommandNumberOfCommunicationBytes  ; Command Number Of Communications Data Bytes (0000 To 005E HEX)
; rung 16
%LD W4.00  ; Report Slave ID
MOV(021) ResponseCommunicationsDataWord3 H20  ; Response Communications Data - Word 3 (92 Bytes Maximum), Fault / Status Flags
MOV(021) ResponseCommunicationsDataWord4 H21  ; Response Communications Data - Word 4 (92 Bytes Maximum), Fault / Status Flags
MOV(021) ResponseCommunicationsDataWord5 H22  ; Response Communications Data - Word 5 (92 Bytes Maximum), Fault / Status Flags

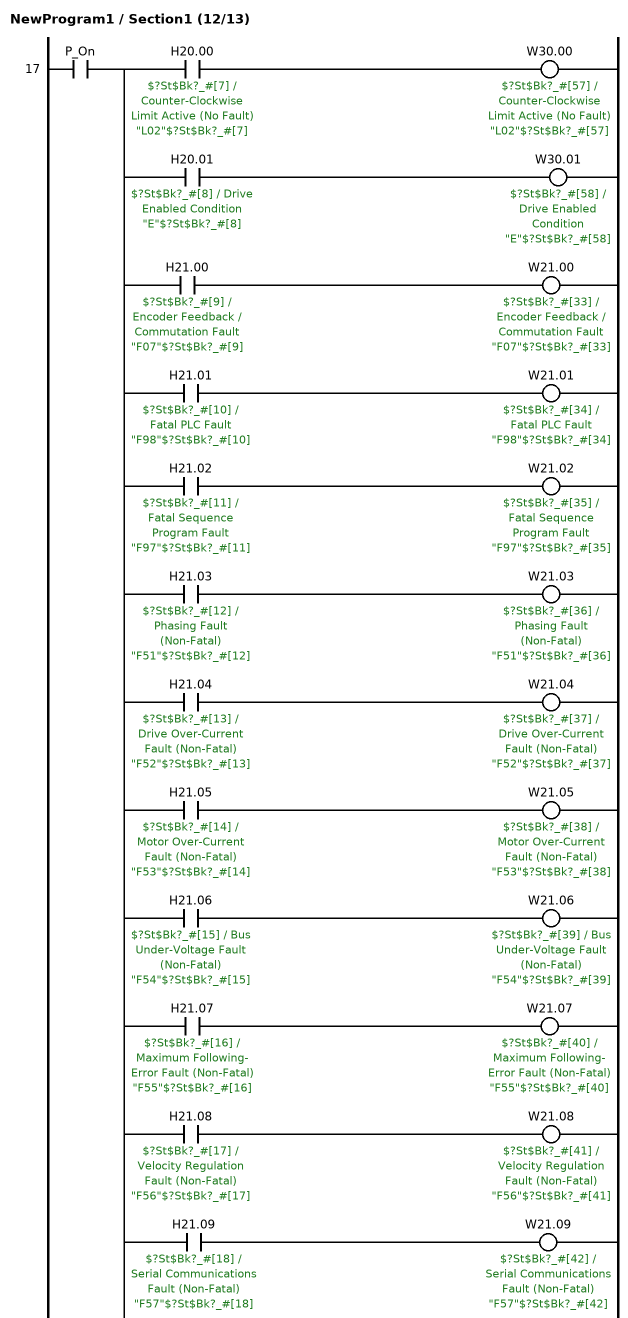
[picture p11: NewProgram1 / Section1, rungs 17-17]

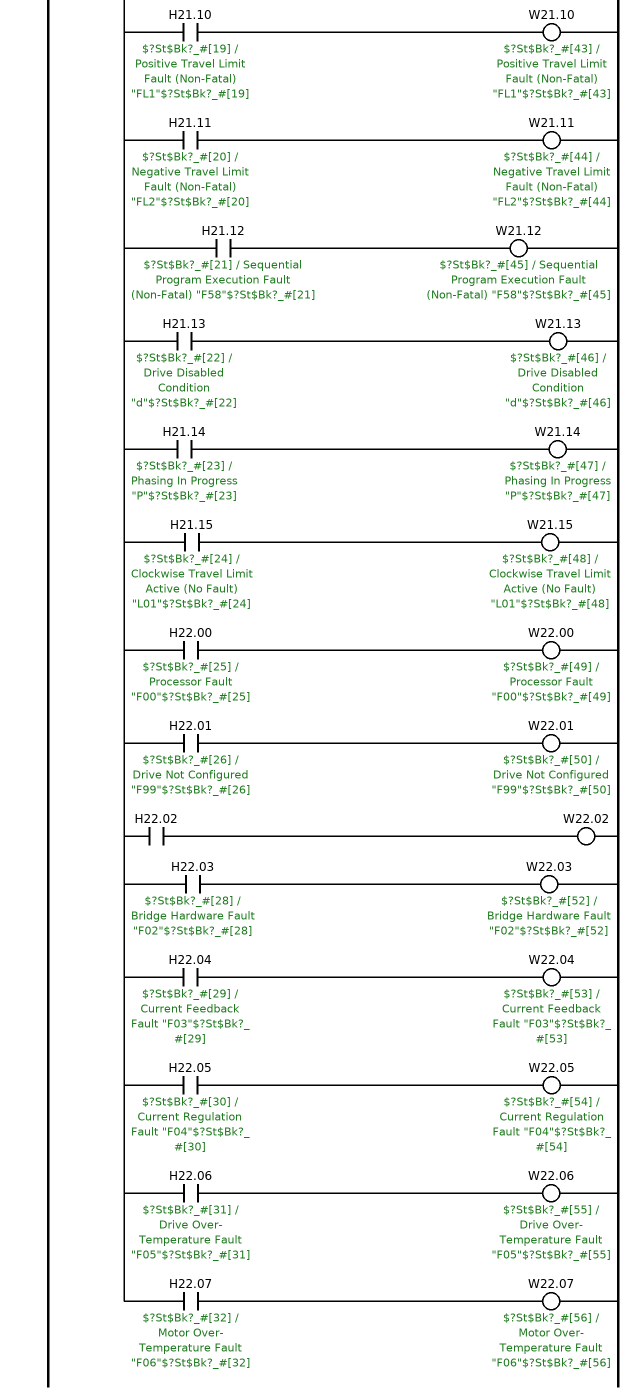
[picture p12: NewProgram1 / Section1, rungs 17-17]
; rung 17
LD P_On
OUT TR0
AND H20.00  ; $?St$Bk?_#[7] / Counter-Clockwise Limit Active (No Fault) "L02"$?St$Bk?_#[7]
OUT W30.00  ; $?St$Bk?_#[57] / Counter-Clockwise Limit Active (No Fault) "L02"$?St$Bk?_#[57]
LD TR0
AND H20.01  ; $?St$Bk?_#[8] / Drive Enabled Condition "E"$?St$Bk?_#[8]
OUT W30.01  ; $?St$Bk?_#[58] / Drive Enabled Condition "E"$?St$Bk?_#[58]
LD TR0
AND H21.00  ; $?St$Bk?_#[9] / Encoder Feedback / Commutation Fault "F07"$?St$Bk?_#[9]
OUT W21.00  ; $?St$Bk?_#[33] / Encoder Feedback / Commutation Fault "F07"$?St$Bk?_#[33]
LD TR0
AND H21.01  ; $?St$Bk?_#[10] / Fatal PLC Fault "F98"$?St$Bk?_#[10]
OUT W21.01  ; $?St$Bk?_#[34] / Fatal PLC Fault "F98"$?St$Bk?_#[34]
LD TR0
AND H21.02  ; $?St$Bk?_#[11] / Fatal Sequence Program Fault "F97"$?St$Bk?_#[11]
OUT W21.02  ; $?St$Bk?_#[35] / Fatal Sequence Program Fault "F97"$?St$Bk?_#[35]
LD TR0
AND H21.03  ; $?St$Bk?_#[12] / Phasing Fault (Non-Fatal) "F51"$?St$Bk?_#[12]
OUT W21.03  ; $?St$Bk?_#[36] / Phasing Fault (Non-Fatal) "F51"$?St$Bk?_#[36]
LD TR0
AND H21.04  ; $?St$Bk?_#[13] / Drive Over-Current Fault (Non-Fatal) "F52"$?St$Bk?_#[13]
OUT W21.04  ; $?St$Bk?_#[37] / Drive Over-Current Fault (Non-Fatal) "F52"$?St$Bk?_#[37]
LD TR0
AND H21.05  ; $?St$Bk?_#[14] / Motor Over-Current Fault (Non-Fatal) "F53"$?St$Bk?_#[14]
OUT W21.05  ; $?St$Bk?_#[38] / Motor Over-Current Fault (Non-Fatal) "F53"$?St$Bk?_#[38]
LD TR0
AND H21.06  ; $?St$Bk?_#[15] / Bus Under-Voltage Fault (Non-Fatal) "F54"$?St$Bk?_#[15]
OUT W21.06  ; $?St$Bk?_#[39] / Bus Under-Voltage Fault (Non-Fatal) "F54"$?St$Bk?_#[39]
LD TR0
AND H21.07  ; $?St$Bk?_#[16] / Maximum Following-Error Fault (Non-Fatal) "F55"$?St$Bk?_#[16]
OUT W21.07  ; $?St$Bk?_#[40] / Maximum Following-Error Fault (Non-Fatal) "F55"$?St$Bk?_#[40]
LD TR0
AND H21.08  ; $?St$Bk?_#[17] / Velocity Regulation Fault (Non-Fatal) "F56"$?St$Bk?_#[17]
OUT W21.08  ; $?St$Bk?_#[41] / Velocity Regulation Fault (Non-Fatal) "F56"$?St$Bk?_#[41]
LD TR0
AND H21.09  ; $?St$Bk?_#[18] / Serial Communications Fault (Non-Fatal) "F57"$?St$Bk?_#[18]
OUT W21.09  ; $?St$Bk?_#[42] / Serial Communications Fault (Non-Fatal) "F57"$?St$Bk?_#[42]
LD TR0
AND H21.10  ; $?St$Bk?_#[19] / Positive Travel Limit Fault (Non-Fatal) "FL1"$?St$Bk?_#[19]
OUT W21.10  ; $?St$Bk?_#[43] / Positive Travel Limit Fault (Non-Fatal) "FL1"$?St$Bk?_#[43]
LD TR0
AND H21.11  ; $?St$Bk?_#[20] / Negative Travel Limit Fault (Non-Fatal) "FL2"$?St$Bk?_#[20]
OUT W21.11  ; $?St$Bk?_#[44] / Negative Travel Limit Fault (Non-Fatal) "FL2"$?St$Bk?_#[44]
LD TR0
AND H21.12  ; $?St$Bk?_#[21] / Sequential Program Execution Fault (Non-Fatal) "F58"$?St$Bk?_#[21]
OUT W21.12  ; $?St$Bk?_#[45] / Sequential Program Execution Fault (Non-Fatal) "F58"$?St$Bk?_#[45]
LD TR0
AND H21.13  ; $?St$Bk?_#[22] / Drive Disabled Condition "d"$?St$Bk?_#[22]
OUT W21.13  ; $?St$Bk?_#[46] / Drive Disabled Condition "d"$?St$Bk?_#[46]
LD TR0
AND H21.14  ; $?St$Bk?_#[23] / Phasing In Progress "P"$?St$Bk?_#[23]
OUT W21.14  ; $?St$Bk?_#[47] / Phasing In Progress "P"$?St$Bk?_#[47]
LD TR0
AND H21.15  ; $?St$Bk?_#[24] / Clockwise Travel Limit Active (No Fault) "L01"$?St$Bk?_#[24]
OUT W21.15  ; $?St$Bk?_#[48] / Clockwise Travel Limit Active (No Fault) "L01"$?St$Bk?_#[48]
LD TR0
AND H22.00  ; $?St$Bk?_#[25] / Processor Fault "F00"$?St$Bk?_#[25]
OUT W22.00  ; $?St$Bk?_#[49] / Processor Fault "F00"$?St$Bk?_#[49]
LD TR0
AND H22.01  ; $?St$Bk?_#[26] / Drive Not Configured "F99"$?St$Bk?_#[26]
OUT W22.01  ; $?St$Bk?_#[50] / Drive Not Configured "F99"$?St$Bk?_#[50]
LD TR0
AND H22.02
OUT W22.02
LD TR0
AND H22.03  ; $?St$Bk?_#[28] / Bridge Hardware Fault "F02"$?St$Bk?_#[28]
OUT W22.03  ; $?St$Bk?_#[52] / Bridge Hardware Fault "F02"$?St$Bk?_#[52]
LD TR0
AND H22.04  ; $?St$Bk?_#[29] / Current Feedback Fault "F03"$?St$Bk?_#[29]
OUT W22.04  ; $?St$Bk?_#[53] / Current Feedback Fault "F03"$?St$Bk?_#[53]
LD TR0
AND H22.05  ; $?St$Bk?_#[30] / Current Regulation Fault "F04"$?St$Bk?_#[30]
OUT W22.05  ; $?St$Bk?_#[54] / Current Regulation Fault "F04"$?St$Bk?_#[54]
LD TR0
AND H22.06  ; $?St$Bk?_#[31] / Drive Over-Temperature Fault "F05"$?St$Bk?_#[31]
OUT W22.06  ; $?St$Bk?_#[55] / Drive Over-Temperature Fault "F05"$?St$Bk?_#[55]
LD TR0
AND H22.07  ; $?St$Bk?_#[32] / Motor Over-Temperature Fault "F06"$?St$Bk?_#[32]
OUT W22.07  ; $?St$Bk?_#[56] / Motor Over-Temperature Fault "F06"$?St$Bk?_#[56]

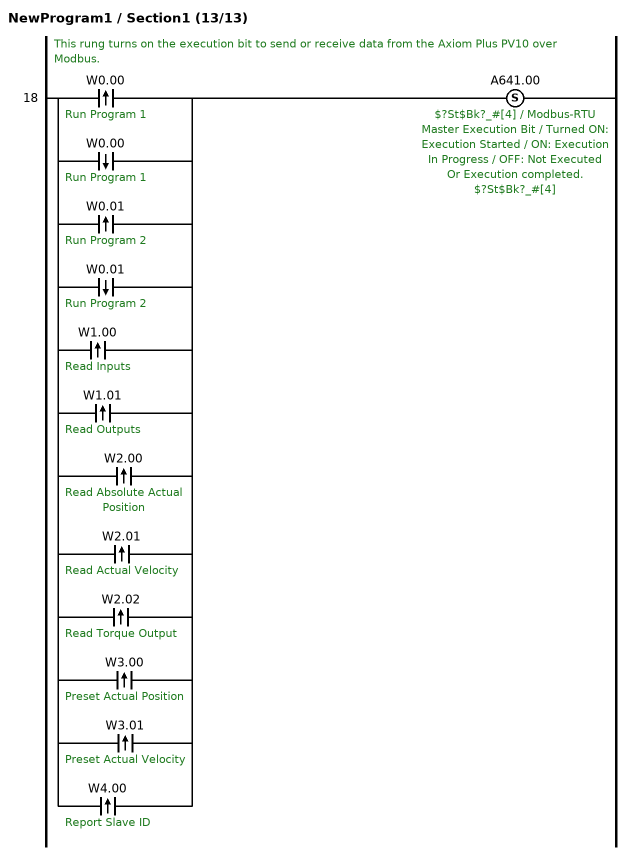
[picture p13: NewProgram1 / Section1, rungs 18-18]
; rung 18: This rung turns on the execution bit to send or receive data from the Axiom Plus PV10 over Modbus.
@LD W0.00  ; Run Program 1
%OR W0.00  ; Run Program 1
@OR W0.01  ; Run Program 2
%OR W0.01  ; Run Program 2
@OR W1.00  ; Read Inputs
@OR W1.01  ; Read Outputs
@OR W2.00  ; Read Absolute Actual Position
@OR W2.01  ; Read Actual Velocity
@OR W2.02  ; Read Torque Output
@OR W3.00  ; Preset Actual Position
@OR W3.01  ; Preset Actual Velocity
@OR W4.00  ; Report Slave ID
SET A641.00  ; $?St$Bk?_#[4] / Modbus-RTU Master Execution Bit / Turned ON: Execution Started / ON: Execution In Progress / OFF: Not Executed Or Execution completed.$?St$Bk?_#[4]

### Section END
; rung 0
END(001)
